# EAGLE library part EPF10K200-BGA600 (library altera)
EPF10K200 FLEX 10K family
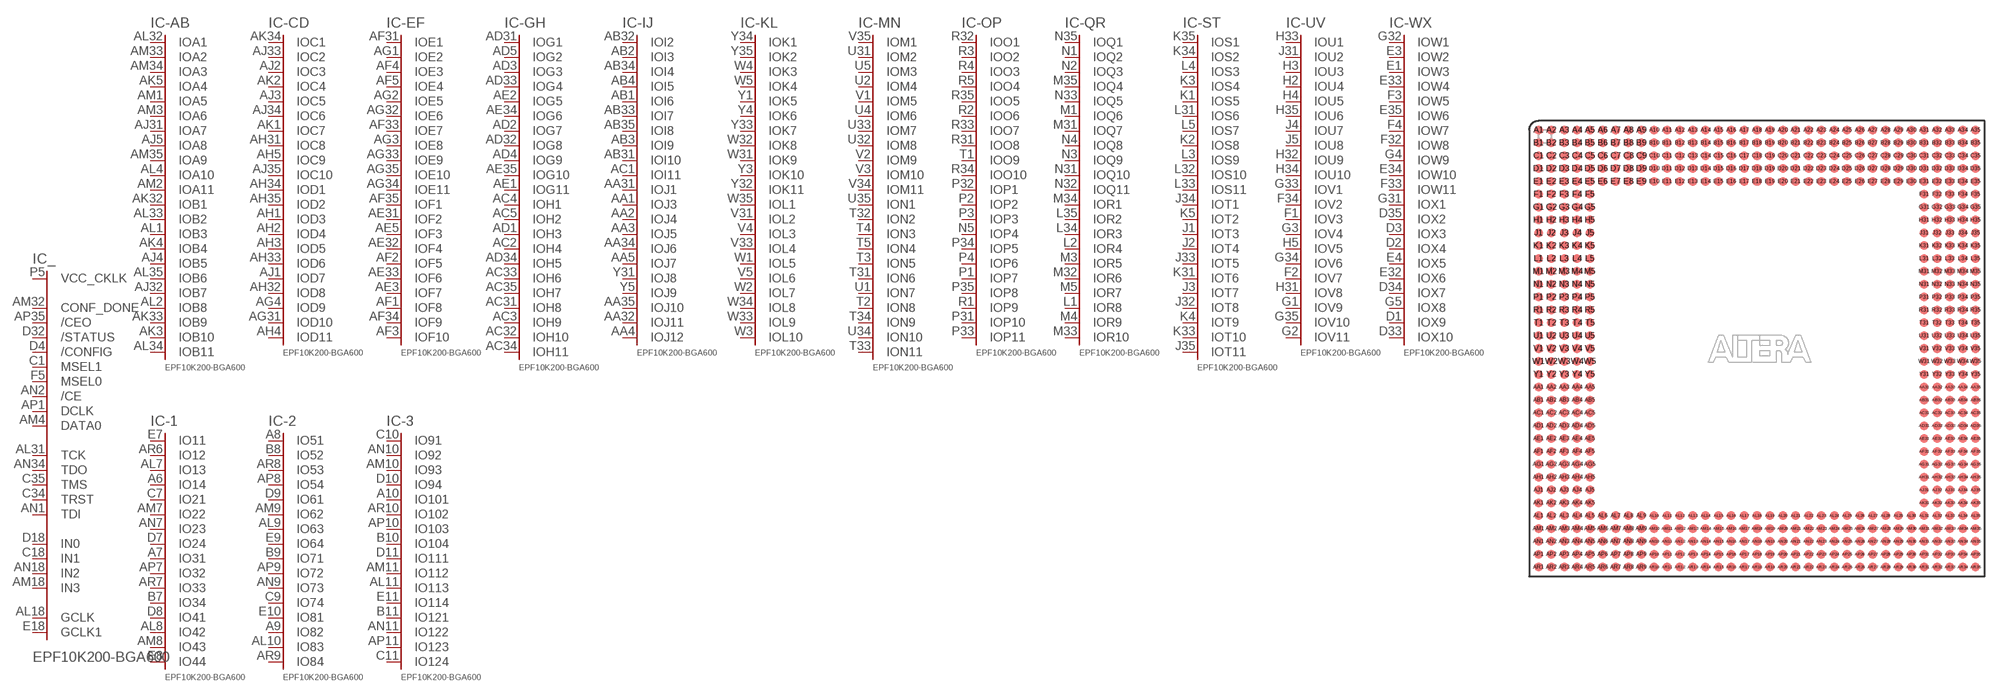
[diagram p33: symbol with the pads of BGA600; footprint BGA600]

Designator prefix IC; gates _=200B600C -AB=AB11 -CD=CD11 -EF=EF10 -GH=GH11 -IJ=IJ12 -KL=KL10 -MN=MN11 -OP=OP11 -QR=QR10 -ST=ST11 -UV=UV11 -WX=WX10 -1=IO44 -2=IO84 -3=IO124 -4=IO164 -5=IO204 -6=IO244 -7=IO284 -8=IO324 -9=IO364 -10=IO404 -11=IO444 -12=IO484 -13=IO524 G1=GND G2=GND G3=GND G4=GND G5=GND G6=GND G7=GND G8=GND G9=GND G10=GND G11=GND G12=GND G13=GND G14=GND G15=GND G16=GND G17=GND G18=GND G19=GND G20=GND G21=GND G22=GND G23=GND G24=GND G25=GND G26=GND G27=GND G28=GND G29=GND G30=GND G31=GND G32=GND G33=GND G34=GND G35=GND G36=GND G37=GND G38=GND G39=GND G40=GND G41=GND G42=GND G43=GND G44=GND G45=GND G46=GND G47=GND G48=GND G49=GND G50=GND G51=GND G52=GND G53=GND G54=GND G55=GND G56=GND G57=GND G58=GND V1=VCCINT V2=VCCINT V3=VCCINT V4=VCCINT V5=VCCINT V6=VCCINT V7=VCCINT V8=VCCINT V9=VCCINT V10=VCCINT V11=VCCINT V12=VCCINT V13=VCCINT V14=VCCINT V15=VCCINT V16=VCCINT V17=VCCINT V18=VCCINT V19=VCCINT V20=VCCINT V21=VCCINT V22=VCCINT V23=VCCINT V24=VCCINT V25=VCCINT V26=VCCINT V27=VCCINT V28=VCCINT VO1=VCCIO VO2=VCCIO VO3=VCCIO VO4=VCCIO VO5=VCCIO VO6=VCCIO VO7=VCCIO VO8=VCCIO VO9=VCCIO VO10=VCCIO VO11=VCCIO VO12=VCCIO VO13=VCCIO VO14=VCCIO VO15=VCCIO VO16=VCCIO VO17=VCCIO VO18=VCCIO VO19=VCCIO VO20=VCCIO VO21=VCCIO VO22=VCCIO VO23=VCCIO VO24=VCCIO VO25=VCCIO VO26=VCCIO VO27=VCCIO VO28=VCCIO VO29=VCCIO

## EPF10K200-BGA600 (MPN: EPF10K200EBC600-1; OC_FARNELL: unknown; OC_NEWARK: 51R8896)  [BGA600]
A1  G27:GND  pwr
A2  G28:GND  pwr
A3  G29:GND  pwr
A4  G30:GND  pwr
A5  G31:GND  pwr
A6  -1:IO14
A7  -1:IO31
A8  -2:IO51
A9  -2:IO82
A10  -3:IO101
A11  V13:VCC  pwr
A12  -4:IO144
A13  -5:IO174
A14  -5:IO191
A15  -6:IO211
A16  -6:IO244
A17  -7:IO263
A18  G32:GND  pwr
A19  V14:VCC  pwr
A20  VO15:VCCIO  pwr
A21  -8:IO314
A22  -9:IO331
A23  -9:IO361
A24  -10:IO384
A25  -10:IO391
A26  -11:IO421
A27  VO16:VCCIO  pwr
A28  -12:IO474
A29  -13:IO491
A30  -13:IO524
A31  G33:GND  pwr
A32  G34:GND  pwr
A33  G35:GND  pwr
A34  G36:GND  pwr
A35  G37:GND  pwr
AA1  -IJ:IOJ3
AA2  -IJ:IOJ4
AA3  -IJ:IOJ5
AA4  -IJ:IOJ12
AA5  -IJ:IOJ7
AA31  -IJ:IOJ1
AA32  -IJ:IOJ11
AA33  V1:VCC  pwr
AA34  -IJ:IOJ6
AA35  -IJ:IOJ10
AB1  -IJ:IOI6
AB2  -IJ:IOI3
AB3  -IJ:IOI9
AB4  -IJ:IOI5
AB5  V2:VCC  pwr
AB31  -IJ:IOI10
AB32  -IJ:IOI2
AB33  -IJ:IOI7
AB34  -IJ:IOI4
AB35  -IJ:IOI8
AC1  -IJ:IOI11
AC2  -GH:IOH4
AC3  -GH:IOH9
AC4  -GH:IOH1
AC5  -GH:IOH2
AC31  -GH:IOH8
AC32  -GH:IOH10
AC33  -GH:IOH6
AC34  -GH:IOH11
AC35  -GH:IOH7
AD1  -GH:IOH3
AD2  -GH:IOG7
AD3  -GH:IOG3
AD4  -GH:IOG9
AD5  -GH:IOG2
AD31  -GH:IOG1
AD32  -GH:IOG8
AD33  -GH:IOG4
AD34  -GH:IOH5
AD35  V3:VCC  pwr
AE1  -GH:IOG11
AE2  -GH:IOG5
AE3  -EF:IOF7
AE4  V4:VCC  pwr
AE5  -EF:IOF3
AE31  -EF:IOF2
AE32  -EF:IOF4
AE33  -EF:IOF6
AE34  -GH:IOG6
AE35  -GH:IOG10
AF1  -EF:IOF8
AF2  -EF:IOF5
AF3  -EF:IOF10
AF4  -EF:IOE3
AF5  -EF:IOE4
AF31  -EF:IOE1
AF32  V5:VCC  pwr
AF33  -EF:IOE7
AF34  -EF:IOF9
AF35  -EF:IOF1
AG1  -EF:IOE2
AG2  -EF:IOE5
AG3  -EF:IOE8
AG4  -CD:IOD9
AG5  V6:VCC  pwr
AG31  -CD:IOD10
AG32  -EF:IOE6
AG33  -EF:IOE9
AG34  -EF:IOE11
AG35  -EF:IOE10
AH1  -CD:IOD3
AH2  -CD:IOD4
AH3  -CD:IOD5
AH4  -CD:IOD11
AH5  -CD:IOC9
AH31  -CD:IOC8
AH32  -CD:IOD8
AH33  -CD:IOD6
AH34  -CD:IOD1
AH35  -CD:IOD2
AJ1  -CD:IOD7
AJ2  -CD:IOC3
AJ3  -CD:IOC5
AJ4  -AB:IOB5
AJ5  -AB:IOA8
AJ31  -AB:IOA7
AJ32  -AB:IOB7
AJ33  -CD:IOC2
AJ34  -CD:IOC6
AJ35  -CD:IOC10
AK1  -CD:IOC7
AK2  -CD:IOC4
AK3  -AB:IOB10
AK4  -AB:IOB4
AK5  -AB:IOA4
AK31  V7:VCC  pwr
AK32  -AB:IOB1
AK33  -AB:IOB9
AK34  -CD:IOC1
AK35  V8:VCC  pwr
AL1  -AB:IOB3
AL2  -AB:IOB8
AL3  V9:VCC  pwr
AL4  -AB:IOA10
AL5  VO1:VCCIO  pwr
AL6  G1:GND  pwr
AL7  -1:IO13
AL8  -1:IO42
AL9  -2:IO63
AL10  -2:IO83
AL11  -3:IO113
AL12  VO2:VCCIO  pwr
AL13  -4:IO153
AL14  -5:IO172
AL15  -5:IO203
AL16  -6:IO222
AL17  -6:IO243
AL18  _:GCLK  in
AL19  -8:IO292
AL20  -8:IO312
AL21  -9:IO343
AL22  -9:IO363
AL23  -10:IO382
AL24  -11:IO412
AL25  -11:IO433
AL26  -12:IO452
AL27  -12:IO472
AL28  -13:IO501
AL29  -13:IO522
AL30  G2:GND  pwr
AL31  _:TCK
AL32  -AB:IOA1
AL33  -AB:IOB2
AL34  -AB:IOB11
AL35  -AB:IOB6
AM1  -AB:IOA5
AM2  -AB:IOA11
AM3  -AB:IOA6
AM4  _:DATA0  in
AM5  VO3:VCCIO  pwr
AM6  G3:GND  pwr
AM7  -1:IO22
AM8  -1:IO43
AM9  -2:IO62
AM10  -3:IO93
AM11  -3:IO112
AM12  -4:IO133
AM13  -4:IO152
AM14  -5:IO183
AM15  -5:IO202
AM16  -6:IO223
AM17  -7:IO251
AM18  _:IN3  in
AM19  VO4:VCCIO  pwr
AM20  -8:IO313
AM21  -9:IO332
AM22  -9:IO364
AM23  -10:IO383
AM24  -10:IO403
AM25  -11:IO422
AM26  VO5:VCCIO  pwr
AM27  -12:IO473
AM28  -13:IO492
AM29  -13:IO523
AM30  G4:GND  pwr
AM31  VO6:VCCIO  pwr
AM32  _:CONF_DONE  in
AM33  -AB:IOA2
AM34  -AB:IOA3
AM35  -AB:IOA9
AN1  _:TDI
AN2  _:/CE  in
AN3  VO7:VCCIO  pwr
AN4  VO8:VCCIO  pwr
AN5  G56:GND  pwr
AN6  G57:GND  pwr
AN7  -1:IO23
AN8  VO9:VCCIO  pwr
AN9  -2:IO73
AN10  -3:IO92
AN11  -3:IO122
AN12  -4:IO132
AN13  -4:IO163
AN14  -5:IO182
AN15  VO10:VCCIO  pwr
AN16  -6:IO232
AN17  -7:IO252
AN18  _:IN2  in
AN19  -7:IO284
AN20  -8:IO302
AN21  -9:IO333
AN22  -9:IO352
AN23  -10:IO371
AN24  -10:IO393
AN25  -11:IO423
AN26  -11:IO442
AN27  -12:IO462
AN28  -13:IO493
AN29  -13:IO512
AN30  G58:GND  pwr
AN31  G5:GND  pwr
AN32  VO11:VCCIO  pwr
AN33  VO12:VCCIO  pwr
AN34  _:TDO
AN35  G6:GND  pwr
AP1  _:DCLK  in
AP2  G7:GND  pwr
AP3  G8:GND  pwr
AP4  G9:GND  pwr
AP5  G10:GND  pwr
AP6  G11:GND  pwr
AP7  -1:IO32
AP8  -2:IO54
AP9  -2:IO72
AP10  -3:IO103
AP11  -3:IO123
AP12  -4:IO143
AP13  -4:IO162
AP14  -5:IO193
AP15  -6:IO212
AP16  -6:IO233
AP17  -7:IO261
AP18  -7:IO273
AP19  -7:IO283
AP20  -8:IO303
AP21  -8:IO322
AP22  -9:IO354
AP23  -10:IO372
AP24  V10:VCC  pwr
AP25  -11:IO413
AP26  -11:IO443
AP27  -12:IO463
AP28  -12:IO482
AP29  -13:IO513
AP30  G12:GND  pwr
AP31  G13:GND  pwr
AP32  G14:GND  pwr
AP33  G15:GND  pwr
AP34  VO13:VCCIO  pwr
AP35  _:/CEO  in
AR1  G16:GND  pwr
AR2  G17:GND  pwr
AR3  G18:GND  pwr
AR4  G19:GND  pwr
AR5  G20:GND  pwr
AR6  -1:IO12
AR7  -1:IO33
AR8  -2:IO53
AR9  -2:IO84
AR10  -3:IO102
AR11  V11:VCC  pwr
AR12  -4:IO142
AR13  -5:IO173
AR14  -5:IO192
AR15  -6:IO213
AR16  -6:IO242
AR17  -7:IO262
AR18  V12:VCC  pwr
AR19  -7:IO272
AR20  -8:IO293
AR21  -8:IO323
AR22  -9:IO342
AR23  VO14:VCCIO  pwr
AR24  -10:IO392
AR25  -10:IO401
AR26  -11:IO432
AR27  -12:IO453
AR28  -12:IO483
AR29  -13:IO502
AR30  G21:GND  pwr
AR31  G22:GND  pwr
AR32  G23:GND  pwr
AR33  G24:GND  pwr
AR34  G25:GND  pwr
AR35  G26:GND  pwr
B1  V15:VCC  pwr
B2  G38:GND  pwr
B3  G39:GND  pwr
B4  G40:GND  pwr
B5  G41:GND  pwr
B6  G42:GND  pwr
B7  -1:IO34
B8  -2:IO52
B9  -2:IO71
B10  -3:IO104
B11  -3:IO121
B12  -4:IO141
B13  -4:IO164
B14  -5:IO194
B15  -6:IO214
B16  -6:IO231
B17  -7:IO264
B18  V16:VCC  pwr
B19  -7:IO274
B20  -8:IO294
B21  -8:IO311
B22  -9:IO344
B23  -9:IO362
B24  -10:IO381
B25  -10:IO404
B26  -11:IO431
B27  -12:IO454
B28  -12:IO471
B29  -13:IO503
B30  -13:IO521
B31  G43:GND  pwr
B32  G44:GND  pwr
B33  G45:GND  pwr
B34  G46:GND  pwr
B35  G47:GND  pwr
C1  _:MSEL1  in
C2  VO17:VCCIO  pwr
C3  VO18:VCCIO  pwr
C4  VO19:VCCIO  pwr
C5  G48:GND  pwr
C6  G49:GND  pwr
C7  -1:IO21
C8  VO20:VCCIO  pwr
C9  -2:IO74
C10  -3:IO91
C11  -3:IO124
C12  -4:IO134
C13  -4:IO161
C14  -5:IO181
C15  VO21:VCCIO  pwr
C16  -6:IO234
C17  -7:IO253
C18  _:IN1  in
C19  -7:IO271
C20  -8:IO291
C21  -8:IO324
C22  -9:IO341
C23  VO22:VCCIO  pwr
C24  -10:IO394
C25  -11:IO411
C26  -11:IO434
C27  -12:IO451
C28  -12:IO484
C29  -13:IO504
C30  G50:GND  pwr
C31  G51:GND  pwr
C32  VO23:VCCIO  pwr
C33  VO24:VCCIO  pwr
C34  _:TRST
C35  _:TMS
D1  -WX:IOX9
D2  -WX:IOX4
D3  -WX:IOX3
D4  _:/CONFIG  in
D5  VO25:VCCIO  pwr
D6  G52:GND  pwr
D7  -1:IO24
D8  -1:IO41
D9  -2:IO61
D10  -3:IO94
D11  -3:IO111
D12  -4:IO131
D13  -4:IO154
D14  -5:IO184
D15  -5:IO201
D16  -6:IO221
D17  -7:IO254
D18  _:IN0  in
D19  -7:IO282
D20  -8:IO304
D21  -8:IO321
D22  -9:IO353
D23  -10:IO374
D24  V17:VCC  pwr
D25  -11:IO414
D26  -11:IO444
D27  -12:IO464
D28  -12:IO481
D29  -13:IO514
D30  G53:GND  pwr
D31  VO26:VCCIO  pwr
D32  _:/STATUS  in
D33  -WX:IOX10
D34  -WX:IOX7
D35  -WX:IOX2
E1  -WX:IOW3
E2  V18:VCC  pwr
E3  -WX:IOW2
E4  -WX:IOX5
E5  VO27:VCCIO  pwr
E6  G54:GND  pwr
E7  -1:IO11
E8  -1:IO44
E9  -2:IO64
E10  -2:IO81
E11  -3:IO114
E12  VO28:VCCIO  pwr
E13  -4:IO151
E14  -5:IO171
E15  -5:IO204
E16  -6:IO224
E17  -6:IO241
E18  _:GCLK1  in
E19  -7:IO281
E20  -8:IO301
E21  -9:IO334
E22  -9:IO351
E23  -10:IO373
E24  -10:IO402
E25  -11:IO424
E26  -11:IO441
E27  -12:IO461
E28  -13:IO494
E29  -13:IO511
E30  G55:GND  pwr
E31  VO29:VCCIO  pwr
E32  -WX:IOX6
E33  -WX:IOW4
E34  -WX:IOW10
E35  -WX:IOW6
F1  -UV:IOV3
F2  -UV:IOV7
F3  -WX:IOW5
F4  -WX:IOW7
F5  _:MSEL0  in
F31  V19:VCC  pwr
F32  -WX:IOW8
F33  -WX:IOW11
F34  -UV:IOV2
F35  V20:VCC  pwr
G1  -UV:IOV9
G2  -UV:IOV11
G3  -UV:IOV4
G4  -WX:IOW9
G5  -WX:IOX8
G31  -WX:IOX1
G32  -WX:IOW1
G33  -UV:IOV1
G34  -UV:IOV6
G35  -UV:IOV10
H1  V21:VCC  pwr
H2  -UV:IOU4
H3  -UV:IOU3
H4  -UV:IOU5
H5  -UV:IOV5
H31  -UV:IOV8
H32  -UV:IOU9
H33  -UV:IOU1
H34  -UV:IOU10
H35  -UV:IOU6
J1  -ST:IOT3
J2  -ST:IOT4
J3  -ST:IOT7
J4  -UV:IOU7
J5  -UV:IOU8
J31  -UV:IOU2
J32  -ST:IOT8
J33  -ST:IOT5
J34  -ST:IOT1
J35  -ST:IOT11
K1  -ST:IOS5
K2  -ST:IOS8
K3  -ST:IOS4
K4  -ST:IOT9
K5  -ST:IOT2
K31  -ST:IOT6
K32  V22:VCC  pwr
K33  -ST:IOT10
K34  -ST:IOS2
K35  -ST:IOS1
L1  -QR:IOR8
L2  -QR:IOR4
L3  -ST:IOS9
L4  -ST:IOS3
L5  -ST:IOS7
L31  -ST:IOS6
L32  -ST:IOS10
L33  -ST:IOS11
L34  -QR:IOR3
L35  -QR:IOR2
M1  -QR:IOQ6
M2  V23:VCC  pwr
M3  -QR:IOR5
M4  -QR:IOR9
M5  -QR:IOR7
M31  -QR:IOQ7
M32  -QR:IOR6
M33  -QR:IOR10
M34  -QR:IOR1
M35  -QR:IOQ4
N1  -QR:IOQ2
N2  -QR:IOQ3
N3  -QR:IOQ9
N4  -QR:IOQ8
N5  -OP:IOP4
N31  -QR:IOQ10
N32  -QR:IOQ11
N33  -QR:IOQ5
N34  V24:VCC  pwr
N35  -QR:IOQ1
P1  -OP:IOP7
P2  -OP:IOP2
P3  -OP:IOP3
P4  -OP:IOP6
P5  _:VCC_CKLK  pas
P31  -OP:IOP10
P32  -OP:IOP1
P33  -OP:IOP11
P34  -OP:IOP5
P35  -OP:IOP8
R1  -OP:IOP9
R2  -OP:IOO6
R3  -OP:IOO2
R4  -OP:IOO3
R5  -OP:IOO4
R31  -OP:IOO8
R32  -OP:IOO1
R33  -OP:IOO7
R34  -OP:IOO10
R35  -OP:IOO5
T1  -OP:IOO9
T2  -MN:ION8
T3  -MN:ION5
T4  -MN:ION3
T5  -MN:ION4
T31  -MN:ION6
T32  -MN:ION2
T33  -MN:ION11
T34  -MN:ION9
T35  V25:VCC  pwr
U1  -MN:ION7
U2  -MN:IOM4
U3  V26:VCC  pwr
U4  -MN:IOM6
U5  -MN:IOM3
U31  -MN:IOM2
U32  -MN:IOM8
U33  -MN:IOM7
U34  -MN:ION10
U35  -MN:ION1
V1  -MN:IOM5
V2  -MN:IOM9
V3  -MN:IOM10
V4  -KL:IOL3
V5  -KL:IOL6
V31  -KL:IOL2
V32  V27:VCC  pwr
V33  -KL:IOL4
V34  -MN:IOM11
V35  -MN:IOM1
W1  -KL:IOL5
W2  -KL:IOL7
W3  -KL:IOL10
W4  -KL:IOK3
W5  -KL:IOK4
W31  -KL:IOK9
W32  -KL:IOK8
W33  -KL:IOL9
W34  -KL:IOL8
W35  -KL:IOL1
Y1  -KL:IOK5
Y2  V28:VCC  pwr
Y3  -KL:IOK10
Y4  -KL:IOK6
Y5  -IJ:IOJ9
Y31  -IJ:IOJ8
Y32  -KL:IOK11
Y33  -KL:IOK7
Y34  -KL:IOK1
Y35  -KL:IOK2

## Footprint BGA600 (pad centres in mm)
Ball Grid Array
smd 0.9 x 0.9: A1 -21.59,21.59; A2 -20.32,21.59; A3 -19.05,21.59; A4 -17.78,21.59; A5 -16.51,21.59; A6 -15.24,21.59; A7 -13.97,21.59; A8 -12.7,21.59; A9 -11.43,21.59; A10 -10.16,21.59; A11 -8.89,21.59; A12 -7.62,21.59; A13 -6.35,21.59; A14 -5.08,21.59; A15 -3.81,21.59; A16 -2.54,21.59; A17 -1.27,21.59; A18 0,21.59; A19 1.27,21.59; A20 2.54,21.59; A21 3.81,21.59; A22 5.08,21.59; A23 6.35,21.59; A24 7.62,21.59; A25 8.89,21.59; A26 10.16,21.59; A27 11.43,21.59; A28 12.7,21.59; A29 13.97,21.59; A30 15.24,21.59; A31 16.51,21.59; A32 17.78,21.59; A33 19.05,21.59; A34 20.32,21.59; A35 21.59,21.59; AA1 -21.59,-3.81; AA2 -20.32,-3.81; AA3 -19.05,-3.81; AA4 -17.78,-3.81; AA5 -16.51,-3.81; AA31 16.51,-3.81; AA32 17.78,-3.81; AA33 19.05,-3.81; AA34 20.32,-3.81; AA35 21.59,-3.81; AB1 -21.59,-5.08; AB2 -20.32,-5.08; AB3 -19.05,-5.08; AB4 -17.78,-5.08; AB5 -16.51,-5.08; AB31 16.51,-5.08; AB32 17.78,-5.08; AB33 19.05,-5.08; AB34 20.32,-5.08; AB35 21.59,-5.08; AC1 -21.59,-6.35; AC2 -20.32,-6.35; AC3 -19.05,-6.35; AC4 -17.78,-6.35; AC5 -16.51,-6.35; AC31 16.51,-6.35; AC32 17.78,-6.35; AC33 19.05,-6.35; AC34 20.32,-6.35; AC35 21.59,-6.35; AD1 -21.59,-7.62; AD2 -20.32,-7.62; AD3 -19.05,-7.62; AD4 -17.78,-7.62; AD5 -16.51,-7.62; AD31 16.51,-7.62; AD32 17.78,-7.62; AD33 19.05,-7.62; AD34 20.32,-7.62; AD35 21.59,-7.62; AE1 -21.59,-8.89; AE2 -20.32,-8.89; AE3 -19.05,-8.89; AE4 -17.78,-8.89; AE5 -16.51,-8.89; AE31 16.51,-8.89; AE32 17.78,-8.89; AE33 19.05,-8.89; AE34 20.32,-8.89; AE35 21.59,-8.89; AF1 -21.59,-10.16; AF2 -20.32,-10.16; AF3 -19.05,-10.16; AF4 -17.78,-10.16; AF5 -16.51,-10.16; AF31 16.51,-10.16; AF32 17.78,-10.16; AF33 19.05,-10.16; AF34 20.32,-10.16; AF35 21.59,-10.16; AG1 -21.59,-11.43; AG2 -20.32,-11.43; AG3 -19.05,-11.43; AG4 -17.78,-11.43; AG5 -16.51,-11.43; AG31 16.51,-11.43; AG32 17.78,-11.43; AG33 19.05,-11.43; AG34 20.32,-11.43; AG35 21.59,-11.43; AH1 -21.59,-12.7; AH2 -20.32,-12.7; AH3 -19.05,-12.7; AH4 -17.78,-12.7; AH5 -16.51,-12.7; AH31 16.51,-12.7; AH32 17.78,-12.7; AH33 19.05,-12.7; AH34 20.32,-12.7; AH35 21.59,-12.7; AJ1 -21.59,-13.97; AJ2 -20.32,-13.97; AJ3 -19.05,-13.97; AJ4 -17.78,-13.97; AJ5 -16.51,-13.97; AJ31 16.51,-13.97; AJ32 17.78,-13.97; AJ33 19.05,-13.97; AJ34 20.32,-13.97; AJ35 21.59,-13.97; AK1 -21.59,-15.24; AK2 -20.32,-15.24; AK3 -19.05,-15.24; AK4 -17.78,-15.24; AK5 -16.51,-15.24; AK31 16.51,-15.24; AK32 17.78,-15.24; AK33 19.05,-15.24; AK34 20.32,-15.24; AK35 21.59,-15.24; AL1 -21.59,-16.51; AL2 -20.32,-16.51; AL3 -19.05,-16.51; AL4 -17.78,-16.51; AL5 -16.51,-16.51; AL6 -15.24,-16.51; AL7 -13.97,-16.51; AL8 -12.7,-16.51; AL9 -11.43,-16.51; AL10 -10.16,-16.51; AL11 -8.89,-16.51; AL12 -7.62,-16.51; AL13 -6.35,-16.51; AL14 -5.08,-16.51; AL15 -3.81,-16.51; AL16 -2.54,-16.51; AL17 -1.27,-16.51; AL18 0,-16.51; AL19 1.27,-16.51; AL20 2.54,-16.51; AL21 3.81,-16.51; AL22 5.08,-16.51; AL23 6.35,-16.51; AL24 7.62,-16.51; AL25 8.89,-16.51; AL26 10.16,-16.51; AL27 11.43,-16.51; AL28 12.7,-16.51; AL29 13.97,-16.51; AL30 15.24,-16.51; AL31 16.51,-16.51; AL32 17.78,-16.51; AL33 19.05,-16.51; AL34 20.32,-16.51; AL35 21.59,-16.51; AM1 -21.59,-17.78; AM2 -20.32,-17.78; AM3 -19.05,-17.78; AM4 -17.78,-17.78; AM5 -16.51,-17.78; AM6 -15.24,-17.78; AM7 -13.97,-17.78; AM8 -12.7,-17.78; AM9 -11.43,-17.78; AM10 -10.16,-17.78; AM11 -8.89,-17.78; AM12 -7.62,-17.78; AM13 -6.35,-17.78; AM14 -5.08,-17.78; AM15 -3.81,-17.78; AM16 -2.54,-17.78; AM17 -1.27,-17.78; AM18 0,-17.78; AM19 1.27,-17.78; AM20 2.54,-17.78; AM21 3.81,-17.78; AM22 5.08,-17.78; AM23 6.35,-17.78; AM24 7.62,-17.78; AM25 8.89,-17.78; AM26 10.16,-17.78; AM27 11.43,-17.78; AM28 12.7,-17.78; AM29 13.97,-17.78; AM30 15.24,-17.78; AM31 16.51,-17.78; AM32 17.78,-17.78; AM33 19.05,-17.78; AM34 20.32,-17.78; AM35 21.59,-17.78; AN1 -21.59,-19.05; AN2 -20.32,-19.05; AN3 -19.05,-19.05; AN4 -17.78,-19.05; AN5 -16.51,-19.05; AN6 -15.24,-19.05; AN7 -13.97,-19.05; AN8 -12.7,-19.05; AN9 -11.43,-19.05; AN10 -10.16,-19.05; AN11 -8.89,-19.05; AN12 -7.62,-19.05; AN13 -6.35,-19.05; AN14 -5.08,-19.05; AN15 -3.81,-19.05; AN16 -2.54,-19.05; AN17 -1.27,-19.05; AN18 0,-19.05; AN19 1.27,-19.05; AN20 2.54,-19.05; AN21 3.81,-19.05; AN22 5.08,-19.05; AN23 6.35,-19.05; AN24 7.62,-19.05; AN25 8.89,-19.05; AN26 10.16,-19.05; AN27 11.43,-19.05; AN28 12.7,-19.05; AN29 13.97,-19.05; AN30 15.24,-19.05; AN31 16.51,-19.05; AN32 17.78,-19.05; AN33 19.05,-19.05; AN34 20.32,-19.05; AN35 21.59,-19.05; AP1 -21.59,-20.32; AP2 -20.32,-20.32; AP3 -19.05,-20.32; AP4 -17.78,-20.32; AP5 -16.51,-20.32; AP6 -15.24,-20.32; AP7 -13.97,-20.32; AP8 -12.7,-20.32; AP9 -11.43,-20.32; AP10 -10.16,-20.32; AP11 -8.89,-20.32; AP12 -7.62,-20.32; AP13 -6.35,-20.32; AP14 -5.08,-20.32; AP15 -3.81,-20.32; AP16 -2.54,-20.32; AP17 -1.27,-20.32; AP18 0,-20.32; AP19 1.27,-20.32; AP20 2.54,-20.32; AP21 3.81,-20.32; AP22 5.08,-20.32; AP23 6.35,-20.32; AP24 7.62,-20.32; AP25 8.89,-20.32; AP26 10.16,-20.32; AP27 11.43,-20.32; AP28 12.7,-20.32; AP29 13.97,-20.32; AP30 15.24,-20.32; AP31 16.51,-20.32; AP32 17.78,-20.32; AP33 19.05,-20.32; AP34 20.32,-20.32; AP35 21.59,-20.32; AR1 -21.59,-21.59; AR2 -20.32,-21.59; AR3 -19.05,-21.59; AR4 -17.78,-21.59; AR5 -16.51,-21.59; AR6 -15.24,-21.59; AR7 -13.97,-21.59; AR8 -12.7,-21.59; AR9 -11.43,-21.59; AR10 -10.16,-21.59; AR11 -8.89,-21.59; AR12 -7.62,-21.59; AR13 -6.35,-21.59; AR14 -5.08,-21.59; AR15 -3.81,-21.59; AR16 -2.54,-21.59; AR17 -1.27,-21.59; AR18 0,-21.59; AR19 1.27,-21.59; AR20 2.54,-21.59; AR21 3.81,-21.59; AR22 5.08,-21.59; AR23 6.35,-21.59; AR24 7.62,-21.59; AR25 8.89,-21.59; AR26 10.16,-21.59; AR27 11.43,-21.59; AR28 12.7,-21.59; AR29 13.97,-21.59; AR30 15.24,-21.59; AR31 16.51,-21.59; AR32 17.78,-21.59; AR33 19.05,-21.59; AR34 20.32,-21.59; AR35 21.59,-21.59; B1 -21.59,20.32; B2 -20.32,20.32; B3 -19.05,20.32; B4 -17.78,20.32; B5 -16.51,20.32; B6 -15.24,20.32; B7 -13.97,20.32; B8 -12.7,20.32; B9 -11.43,20.32; B10 -10.16,20.32; B11 -8.89,20.32; B12 -7.62,20.32; B13 -6.35,20.32; B14 -5.08,20.32; B15 -3.81,20.32; B16 -2.54,20.32; B17 -1.27,20.32; B18 0,20.32; B19 1.27,20.32; B20 2.54,20.32; B21 3.81,20.32; B22 5.08,20.32; B23 6.35,20.32; B24 7.62,20.32; B25 8.89,20.32; B26 10.16,20.32; B27 11.43,20.32; B28 12.7,20.32; B29 13.97,20.32; B30 15.24,20.32; B31 16.51,20.32; B32 17.78,20.32; B33 19.05,20.32; B34 20.32,20.32; B35 21.59,20.32; C1 -21.59,19.05; C2 -20.32,19.05; C3 -19.05,19.05; C4 -17.78,19.05; C5 -16.51,19.05; C6 -15.24,19.05; C7 -13.97,19.05; C8 -12.7,19.05; C9 -11.43,19.05; C10 -10.16,19.05; C11 -8.89,19.05; C12 -7.62,19.05; C13 -6.35,19.05; C14 -5.08,19.05; C15 -3.81,19.05; C16 -2.54,19.05; C17 -1.27,19.05; C18 0,19.05; C19 1.27,19.05; C20 2.54,19.05; C21 3.81,19.05; C22 5.08,19.05; C23 6.35,19.05; C24 7.62,19.05; C25 8.89,19.05; C26 10.16,19.05; C27 11.43,19.05; C28 12.7,19.05; C29 13.97,19.05; C30 15.24,19.05; C31 16.51,19.05; C32 17.78,19.05; C33 19.05,19.05; C34 20.32,19.05; C35 21.59,19.05; D1 -21.59,17.78; D2 -20.32,17.78; D3 -19.05,17.78; D4 -17.78,17.78; D5 -16.51,17.78; D6 -15.24,17.78; D7 -13.97,17.78; D8 -12.7,17.78; D9 -11.43,17.78; D10 -10.16,17.78; D11 -8.89,17.78; D12 -7.62,17.78; D13 -6.35,17.78; D14 -5.08,17.78; D15 -3.81,17.78; D16 -2.54,17.78; D17 -1.27,17.78; D18 0,17.78; D19 1.27,17.78; D20 2.54,17.78; D21 3.81,17.78; D22 5.08,17.78; D23 6.35,17.78; D24 7.62,17.78; D25 8.89,17.78; D26 10.16,17.78; D27 11.43,17.78; D28 12.7,17.78; D29 13.97,17.78; D30 15.24,17.78; D31 16.51,17.78; D32 17.78,17.78; D33 19.05,17.78; D34 20.32,17.78; D35 21.59,17.78; E1 -21.59,16.51; E2 -20.32,16.51; E3 -19.05,16.51; E4 -17.78,16.51; E5 -16.51,16.51; E6 -15.24,16.51; E7 -13.97,16.51; E8 -12.7,16.51; E9 -11.43,16.51; E10 -10.16,16.51; E11 -8.89,16.51; E12 -7.62,16.51; E13 -6.35,16.51; E14 -5.08,16.51; E15 -3.81,16.51; E16 -2.54,16.51; E17 -1.27,16.51; E18 0,16.51; E19 1.27,16.51; E20 2.54,16.51; E21 3.81,16.51; E22 5.08,16.51; E23 6.35,16.51; E24 7.62,16.51; E25 8.89,16.51; E26 10.16,16.51; E27 11.43,16.51; E28 12.7,16.51; E29 13.97,16.51; E30 15.24,16.51; E31 16.51,16.51; E32 17.78,16.51; E33 19.05,16.51; E34 20.32,16.51; E35 21.59,16.51; F1 -21.59,15.24; F2 -20.32,15.24; F3 -19.05,15.24; F4 -17.78,15.24; F5 -16.51,15.24; F31 16.51,15.24; F32 17.78,15.24; F33 19.05,15.24; F34 20.32,15.24; F35 21.59,15.24; G1 -21.59,13.97; G2 -20.32,13.97; G3 -19.05,13.97; G4 -17.78,13.97; G5 -16.51,13.97; G31 16.51,13.97; G32 17.78,13.97; G33 19.05,13.97; G34 20.32,13.97; G35 21.59,13.97; H1 -21.59,12.7; H2 -20.32,12.7; H3 -19.05,12.7; H4 -17.78,12.7; H5 -16.51,12.7; H31 16.51,12.7; H32 17.78,12.7; H33 19.05,12.7; H34 20.32,12.7; H35 21.59,12.7; J1 -21.59,11.43; J2 -20.32,11.43; J3 -19.05,11.43; J4 -17.78,11.43; J5 -16.51,11.43; J31 16.51,11.43; J32 17.78,11.43; J33 19.05,11.43; J34 20.32,11.43; J35 21.59,11.43; K1 -21.59,10.16; K2 -20.32,10.16; K3 -19.05,10.16; K4 -17.78,10.16; K5 -16.51,10.16; K31 16.51,10.16; K32 17.78,10.16; K33 19.05,10.16; K34 20.32,10.16; K35 21.59,10.16; L1 -21.59,8.89; L2 -20.32,8.89; L3 -19.05,8.89; L4 -17.78,8.89; L5 -16.51,8.89; L31 16.51,8.89; L32 17.78,8.89; L33 19.05,8.89; L34 20.32,8.89; L35 21.59,8.89; M1 -21.59,7.62; M2 -20.32,7.62; M3 -19.05,7.62; M4 -17.78,7.62; M5 -16.51,7.62; M31 16.51,7.62; M32 17.78,7.62; M33 19.05,7.62; M34 20.32,7.62; M35 21.59,7.62; N1 -21.59,6.35; N2 -20.32,6.35; N3 -19.05,6.35; N4 -17.78,6.35; N5 -16.51,6.35; N31 16.51,6.35; N32 17.78,6.35; N33 19.05,6.35; N34 20.32,6.35; N35 21.59,6.35; P1 -21.59,5.08; P2 -20.32,5.08; P3 -19.05,5.08; P4 -17.78,5.08; P5 -16.51,5.08; P31 16.51,5.08; P32 17.78,5.08; P33 19.05,5.08; P34 20.32,5.08; P35 21.59,5.08; R1 -21.59,3.81; R2 -20.32,3.81; R3 -19.05,3.81; R4 -17.78,3.81; R5 -16.51,3.81; R31 16.51,3.81; R32 17.78,3.81; R33 19.05,3.81; R34 20.32,3.81; R35 21.59,3.81; T1 -21.59,2.54; T2 -20.32,2.54; T3 -19.05,2.54; T4 -17.78,2.54; T5 -16.51,2.54; T31 16.51,2.54; T32 17.78,2.54; T33 19.05,2.54; T34 20.32,2.54; T35 21.59,2.54; U1 -21.59,1.27; U2 -20.32,1.27; U3 -19.05,1.27; U4 -17.78,1.27; U5 -16.51,1.27; U31 16.51,1.27; U32 17.78,1.27; U33 19.05,1.27; U34 20.32,1.27; U35 21.59,1.27; V1 -21.59,0; V2 -20.32,0; V3 -19.05,0; V4 -17.78,0; V5 -16.51,0; V31 16.51,0; V32 17.78,0; V33 19.05,0; V34 20.32,0; V35 21.59,0; W1 -21.59,-1.27; W2 -20.32,-1.27; W3 -19.05,-1.27; W4 -17.78,-1.27; W5 -16.51,-1.27; W31 16.51,-1.27; W32 17.78,-1.27; W33 19.05,-1.27; W34 20.32,-1.27; W35 21.59,-1.27; Y1 -21.59,-2.54; Y2 -20.32,-2.54; Y3 -19.05,-2.54; Y4 -17.78,-2.54; Y5 -16.51,-2.54; Y31 16.51,-2.54; Y32 17.78,-2.54; Y33 19.05,-2.54; Y34 20.32,-2.54; Y35 21.59,-2.54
